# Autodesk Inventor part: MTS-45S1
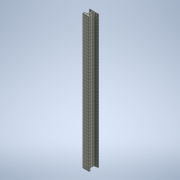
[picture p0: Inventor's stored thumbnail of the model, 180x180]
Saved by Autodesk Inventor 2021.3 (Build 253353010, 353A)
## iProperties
Created: 2021-11
Part Number: MTS-45S1
Material: Concrete, Precast
Document SubType Name: Modeling
Designer: u1426
Density: 2.40731 g/cm^3
Appearance: Smooth Precast Structural
Author: u1426
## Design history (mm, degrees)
sketch "Sketch1"
  geometry: L1 (0, 0)-(-400.05, 0); L2 (-431.8, -31.75)-(-431.8, -143.319); L3 (-390.596, -202.776)-(-208.052, -271.231); L4 (-76.2, -461.493)-(-76.2, -849.936); L5 (-267.326, -1052.777)-(-573.764, -1071.017); L6 (-609.6, -1109.05)-(-609.6, -1143); L7 (0, 0)-(400.05, 0); L8 (431.8, -31.75)-(431.8, -143.319); L9 (390.596, -202.776)-(208.052, -271.231); L10 (76.2, -461.493)-(76.2, -849.936); L11 (267.326, -1052.777)-(573.764, -1071.017); L12 (609.6, -1109.05)-(609.6, -1143); L13 (609.6, -1143)-(-609.6, -1143); L14 (431.8, -31.75)-(400.05, 0); L15 (-400.05, 0)-(-431.8, -31.75); A1 r 38.1 centre (571.5, -1109.05) between (609.6, -1109.05) and (573.764, -1071.017); A2 r 38.1 centre (-571.5, -1109.05) between (-573.764, -1071.017) and (-609.6, -1109.05); A3 r 203.2 centre (-279.4, -849.936) between (-267.326, -1052.777) and (-76.2, -849.936); A4 r 203.2 centre (279.4, -849.936) between (76.2, -849.936) and (267.326, -1052.777); A5 r 203.2 centre (279.4, -461.493) between (208.052, -271.231) and (76.2, -461.493); A6 r 203.2 centre (-279.4, -461.493) between (-76.2, -461.493) and (-208.052, -271.231); A7 r 63.5 centre (368.3, -143.319) between (390.596, -202.776) and (431.8, -143.319); A8 r 63.5 centre (-368.3, -143.319) between (-431.8, -143.319) and (-390.596, -202.776); 10 further points
  constraints: 30 end point, 20 point on line, 16 point on circle, 16 tangent, 8 centre point, 5 equal radius, 3 parallel, 3 perpendicular, 2 horizontal, 1 vertical
  dimensions: "d0" = 431.8 distance of L1.start point (-431.8, 0); "d1" = 187.325 distance of point (-431.8, 0) point (-431.8, -187.325); "d2" = 355.6 horizontal distance of point (-431.8, -187.325) point (-76.2, -320.675); "d3" = 133.35 vertical distance of point (-431.8, -187.325) point (-76.2, -320.675); "d4" = 31.75 vertical distance of point (-76.2, -1041.4) point (-609.6, -1073.15); "d5" = 69.85 distance of point (-609.6, -1073.15) L6.end; "d7" = 533.4 horizontal distance of point (-76.2, -1041.4) point (-609.6, -1073.15); "d8" = 431.8 distance of L1.start point (431.8, 0); "d9" = 187.325 distance of point (431.8, 0) point (431.8, -187.325); "d10" = 355.6 horizontal distance of point (431.8, -187.325) point (76.2, -320.675); "d11" = 133.35 vertical distance of point (431.8, -187.325) point (76.2, -320.675); "d12" = 533.4 horizontal distance of point (76.2, -1041.4) point (609.6, -1073.15); "d13" = 31.75 vertical distance of point (76.2, -1041.4) point (609.6, -1073.15); "d14" = 1143 distance between parallel lines of L1 L13; "d15" = 69.85 distance of point (609.6, -1073.15) L12.end; "d16" = 1219.2 distance between parallel lines of L6 L12 (derived); "d17" = 863.6 distance between parallel lines of L2 L8 (derived); "d18" = 152.4 distance between parallel lines of L4 L10 (derived); "d19" = 38.1 radius of A1; "d20" = 203.2 radius of A3; "d21" = 63.5 radius of A7; "d22" = 31.75 distance of L8.start point (431.8, 0); "d23" = 31.75 distance of L7.end point (431.8, 0) (= d22); "d24" = 31.75 distance of L1.end point (-431.8, 0) (= d22); "d25" = 31.75 distance of L2.start point (-431.8, 0) (= d24)
extrude "Extrusion1" new body sketch "Sketch1" distance "d26" = 18516.6; taper "d27" = 0 deg
sketch "Sketch2"
  geometry: L1 (681.507, 0)-(681.507, -18516.6) reference; L2 (0, 0)-(388.443, 0) reference; 2 further points
  dimensions: "d35" = 406.4 distance from line of point (275.107, -139.7) L1; "d36" = 139.7 distance from line of point (275.107, -139.7) L2
hole "Hole1" sketch "Sketch2" at (275.107, -139.7) diameter "d28" = 38.1; stored, may be unused: countersink angle "d32" = 82 deg, drill point angle "d34" = 118 deg; dims "d29" = 19.05, "d30" = 9.525, "d31" = 6.35, "d33" = 25.4
sketch "Sketch3"
  geometry: L1 (-609.6, 1143)-(609.6, 1143) reference; L2 (-609.6, 1143)-(609.6, 1143); L3 (609.6, 1143)-(609.6, 939.8); L4 (609.6, 939.8)-(-609.6, 939.8); L5 (-609.6, 939.8)-(-609.6, 1143); 2 further points
  constraints: 8 end point, 2 parallel, 1 horizontal, 1 perpendicular
  dimensions: "d37" = 203.2 distance of L2.end L3.end
extrude "Extrusion2" cut sketch "Sketch3" distance "d38" = 139.7; taper "d39" = 0 deg
sketch "Sketch4"
  geometry: L1 (-31.75, 18516.6)-(-31.75, 0) reference; L2 (-31.75, 18402.3)-(-6.35, 18402.3); L3 (-6.35, 18402.3)-(-6.35, 18249.9); L4 (-6.35, 18249.9)-(-31.75, 18249.9); L5 (-31.75, 18249.9)-(-31.75, 18402.3); L6 (-31.75, 114.3)-(-6.35, 114.3); L7 (-6.35, 114.3)-(-6.35, 266.7); L8 (-6.35, 266.7)-(-31.75, 266.7); L9 (-31.75, 266.7)-(-31.75, 114.3); L10 (0, 0)-(-31.75, 0) reference; L11 (-31.75, 18516.6)-(0, 18516.6) reference; 3 further points
  constraints: 16 end point, 4 parallel, 3 point on line, 2 horizontal, 2 perpendicular
  dimensions: "d40" = 25.4 distance of L3.end L4.end; "d41" = 152.4 distance of L2.end L3.end; "d42" = 152.4 distance of L7.end L6.end; "d43" = 114.3 distance between parallel lines of L6 L10; "d44" = 114.3 distance between parallel lines of L2 L11
extrude "Extrusion3" cut sketch "Sketch4" extent not by distance; stored distance "d45" = 0; taper "d46" = 0 deg
sketch "Sketch5"
  geometry: L1 (850.9, 0)-(0, 0) reference; L2 (0, 0)-(850.9, 0); L3 (825.5, -25.4)-(857.25, 6.35) reference; L4 (25.4, -25.4)-(825.5, -25.4) reference; L5 (-6.35, 6.35)-(25.4, -25.4) reference; 1 further point
  constraints: 2 end point, 1 horizontal, 1 point on line
extrude "Extrusion4" new body sketch "Sketch5" distance "d47" = 152.4; taper "d48" = 0 deg
sketch "Sketch6"
  geometry: L1 (25.4, -25.4)-(0, 0) reference; L2 (825.5, -25.4)-(25.4, -25.4) reference; L3 (850.9, 0)-(825.5, -25.4) reference; L4 (850.9, 0)-(0, 0); 2 further points
  constraints: 2 end point, 1 horizontal, 1 point on line
extrude "Extrusion5" new body sketch "Sketch6" distance "d49" = 152.4; taper "d50" = 0 deg
body "Solid1"
body "Solid2"
body "Solid3"
